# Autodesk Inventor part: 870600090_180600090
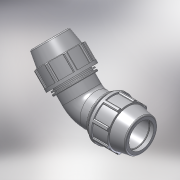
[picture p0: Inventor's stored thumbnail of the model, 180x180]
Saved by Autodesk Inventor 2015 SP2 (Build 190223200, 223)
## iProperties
Created: 2017-02
Part Number: 870600090_180600090
Material: PVC-Piping
Description: PLASSON 45° ELBOW 90-90
Document SubType Name: Modeling
Designer: KIM
Mass: 92.6774 g
Surface Area: 199.44 cm^2
Volume: 66.1981 cm^3
Density: 1.4 g/cm^3
Appearance: Smooth - White
Author: Кирилл
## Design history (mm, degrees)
derived "87060.ipt"
feature "Solid1::87060.ipt"
tag "TaggingFeature1"
body "Solid1"
other parameters: "d4" = 16.16667, "d5" = 48.5, "d7" = 152, "d9" = 27.71429, "d11" = 6.46667, "d13" = 120 deg, "d14" = 117, "d15" = 10 deg, "d16" = 132.24, "d18" = 4.5, "d19" = 35 deg, "d20" = 17.5 deg, "d21" = 141.36, "d23" = 0, "d25" = 360 deg, "d27" = 3.04, "d33" = 1.8, "d42" = 65.96, "d43" = 4.56, "d46" = 1.8, "d51" = 194, "d59" = 135 deg, "d63" = 164, "d64" = 81, "d67" = 114, "d68" = 11.64, "d70" = 45 deg, "d72" = 10.13333, "d73" = 0, "d75" = 135 deg, "d77" = 129.5952, "d78" = 3.88, "E_" = 152, "A_" = 194, "l_" = 164
